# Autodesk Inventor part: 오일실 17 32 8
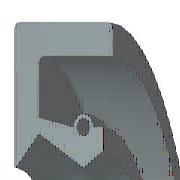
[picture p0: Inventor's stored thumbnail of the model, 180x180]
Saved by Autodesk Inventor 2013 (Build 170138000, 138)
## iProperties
IsCustomPart: 1
Created: 2012-02
Part Number: 오일실 17 32 8
Material: 고무
Description: 오일-실
Document SubType Name: Modeling
Standard: KS B 2804
Designer: mduedu
Standards Organization: KS
Language: ko-KR
Size Designation: D - 17 32 8
Categories: <MemberInstance><Categories><Category DisplayName="샤프트 부품" InternalName="7f7aeb1f-a693-4053-b835-cee3144e0d98" Mnemonic="SHFT"><Category DisplayName="실링" Intern
Density: 0.93 g/cm^3
Mass: 2.28027 g
Surface Area: 32.1224 cm^2
Volume: 2.45191 cm^3
Author: mduedu
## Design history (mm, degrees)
revolve "본체" stored, may be unused: angle "d17" = 90 deg
revolve "스프링1" stored, may be unused: angle "d18" = 90 deg
body "Solid1"
sketch "스케치1"
  geometry: L1 (0, 16)-(8, 16); L2 (8, 14.25)-(1.75, 14.25); L3 (1.75, 10.25)-(4.9, 8.5); L4 (4.9, 8.5)-(0, 8.5); L5 (0, 0)-(9.586, 0) reference; L6 (4.9, 8.5)-(6.3, 9.375); L7 (0, 18)-(0, -3) reference; L8 (-1.941, 0)-(11.507, 0) reference; L9 (4.2, 10.6)-(1.75, 11.21); L10 (1.75, 11.21)-(1.75, 14.25); L11 (0, 16)-(0, 8.588); L12 (4.9, 8.5)-(0, 8.5); L13 (1.75, 10.25)-(0.152, 8.528); L14 (8, 16)-(8, 14.25); L15 (5.6, 10.6)-(6.3, 10.6); L16 (6.3, 10.6)-(6.3, 9.375); C1 r 0.455 at (4.9, 10.6); A1 r 0.7 centre (4.9, 10.6) between (5.6, 10.6) and (4.2, 10.6); A2 r 0.088 centre (0.088, 8.588) between (0, 8.588) and (0.152, 8.528); 1 further point
  constraints: 28 end point, 5 horizontal alignment, 5 point on line, 4 point on circle, 4 vertical alignment, 3 centre point, 3 tangent, 2 collinear, 2 horizontal, 2 perpendicular, 1 coincident, 1 parallel
  dimensions: "d0" = 32 diameter of L1 L5 (= SD2); "d1" = 1.75 distance of L1.end L2.start (= SD); "d2" = 0.91 diameter of C1 (= SPDI); "d3" = 1.4 diameter of A1 (= SPDA); "d4" = 17 diameter of L3.end L5 (= NND); "d5" = 20.5 diameter of L3.start L5 (= TKDM); "d7" = 22.42 diameter of L9.end L5 (= TKDM + 0.24 x SWDT); "d8" = 1.75 distance between parallel lines of L11 L10 (= SD); "d9" = 4.9 distance from line of L11 C1.centre (= SPDST); "d10" = 21.2 diameter of C1.centre L5 (= HLDM); "d11" = 0.0875 radius of A2 (= 0.25 x LAB); "d12" = 6.3 distance between parallel lines of L11 L16 (= SDI); "d13" = 18.75 diameter of L6.end L5 (= ABDM); "d14" = 8 distance from line of L11 L1.end (= SWDT)
fillet "모깎기1" dims "d6" = 0.3 (= RR)
other parameters: "SD2" = 32 [user parameter; used in 1 equation term], "SWDT" = 8 [user parameter; used in 2 equation terms], "RR" = 0.3 [user parameter; used in 1 equation term], "SD" = 1.75 [user parameter; used in 2 equation terms], "NND" = 17 [user parameter; used in 1 equation term], "SPDA" = 1.4 [user parameter; used in 1 equation term], "SPDI" = 0.91 [user parameter; used in 1 equation term], "TKDM" = 20.5 [user parameter; used in 2 equation terms], "HLDM" = 21.2 [user parameter; used in 1 equation term], "ABDM" = 18.75 [user parameter; used in 1 equation term], "SDI" = 6.3 [user parameter; used in 1 equation term], "SPDST" = 4.9 [user parameter; used in 1 equation term], "LAB" = 0.35 [user parameter; used in 1 equation term], "d15" = 0, "d16" = 0, "d19" = 0
